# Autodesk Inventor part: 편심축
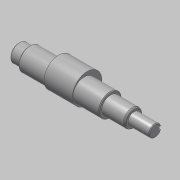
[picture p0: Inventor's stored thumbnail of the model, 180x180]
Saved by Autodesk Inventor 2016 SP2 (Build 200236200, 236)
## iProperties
Created: 2015-10
Part Number: 편심축
Document SubType Name: Modeling
Designer: mdu
Density: 7.86 g/cm^3
Material: 강철, 연강
Mass: 1127.7 g
Surface Area: 205.352 cm^2
Volume: 143.474 cm^3
Appearance: 강철
Author: mdu
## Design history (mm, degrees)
sketch "스케치1"
  geometry: L1 (-20.5, -41.331)-(-20.5, 32.669) reference; L2 (7.5, -30.031)-(7.5, 21.369) reference; L3 (135.5, -30.331)-(135.5, 21.669) reference; L4 (121.5, 21.369)-(121.5, -30.031) reference; L5 (184.5, -4.331)-(-7.5, -4.331); L6 (184.5, -4.331)-(184.5, 4.169); L7 (154.5, 8.169)-(121.5, 8.169); L8 (121.5, 8.169)-(121.5, 11.669); L9 (121.5, 11.669)-(7.5, 11.669); L10 (7.5, 11.669)-(7.5, 8.169); L11 (7.5, 8.169)-(-7.5, 8.169); L12 (-7.5, 8.169)-(-7.5, -4.331); L13 (154.5, 8.169)-(154.5, 4.169); L14 (154.5, 4.169)-(184.5, 4.169); C1 r 32.5 at (64.5, -4.331) reference; 1 further point
  constraints: 21 end point, 8 perpendicular, 5 point on line, 1 collinear
  dimensions: "d1" = 25 diameter of L11 L5; "d2" = 32 diameter of L9 L5; "d4" = 15 distance of L10.end L11.end; "d15" = 33 distance of L7.start L7.end; "d26" = 30 distance of L13.end L6.end; "d36" = 17 diameter of L14 L5
revolve "회전1" sketch "스케치1" stored, may be unused: angle "d6" = 90 deg
node "작업 평면1"
sketch "스케치2"
  geometry: C1 r 16 at (0, 0) reference; C2 r 20.75 at (0, 4)
  constraints: 1 centre point, 1 vertical alignment
  dimensions: "d34" = 4 distance of C2.centre C1.centre; "d35" = 41.5 diameter of C2
extrude "돌출1" join sketch "스케치2" stored distance "d9" = 40; taper "d10" = 0 deg
chamfer "모따기1" distance "d11" = 1; stored, may be unused: second distance "d12" = 2, angle "d13" = 45 deg
node "작업 평면2"
sketch "스케치3"
  geometry: L1 (-15, -7.5)-(-15, 7.5) reference; L2 (-15, 2.5)-(0.5, 2.5); L3 (0.5, -2.5)-(-15, -2.5); A1 r 2.5 centre (0.5, 0) between (0.5, -2.5) and (0.5, 2.5); 2 further points
  constraints: 4 end point, 2 perpendicular, 2 point on circle, 2 point on line, 2 tangent, 1 centre point, 1 horizontal alignment, 1 midpoint
  dimensions: "d16" = 18 dimension on A1 L1; "d17" = 5 distance between parallel lines of L3 L2
extrude "돌출2" cut sketch "스케치3" distance "d18" = 3; taper "d19" = 0 deg
chamfer "모따기2" distance "d37" = 2.15; stored, may be unused: second distance "d38" = 2, angle "d39" = 30 deg
fillet "모깎기1" dims "d40" = 1, "d41" = 2
node "솔리드1"
node "참조1"
node "참조2"
node "참조3"
node "참조4"
node "참조5"
other parameters: "d30" = 35
